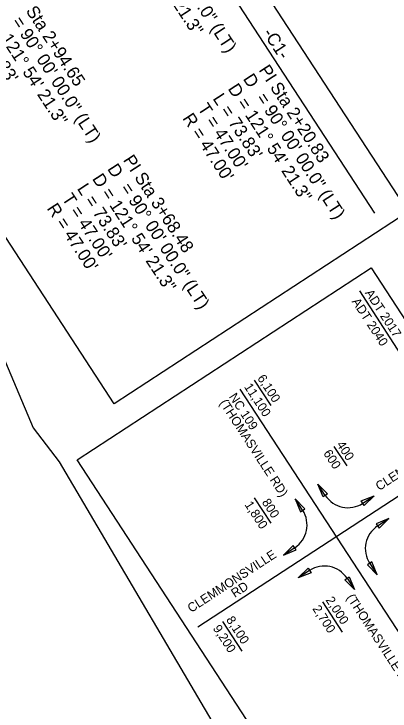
# Model space of a CAD drawing. Extents: x 1639622 to 2864602, y 842655 to 973236.
# Drawn here: x 1640955.4 to 1641163.7, y 843105.8 to 843491.5 of the extents above; entities that cross this region are included whole.
import ezdxf

# ---------------------------------------------------------------- set-up
doc = ezdxf.new("R2010")
doc.units = 0
for name, color, linetype in [('Default', 7, 'Continuous'), ('Prop Horizontal Alignment Curve and Spiral Data', 7, 'Continuous'), ('Sheet Clip Boundary CELL', 7, 'Continuous')]:
    doc.layers.add(name, color=color, linetype=linetype)

msp = doc.modelspace()

# ---------------------------------------------------------------- linework, layer by layer
at = {"layer": 'Default'}
for p, q in [((1641146.66, 843338.21), (1641169.32, 843303.49)), ((1641088.4, 843288.94), (1641097.65, 843274.76)), ((1641080.54, 843283.82), (1641187.11, 843120.51)), ((1641210.87, 843252.44), (1641057.23, 843152.18)), ((1641132.62, 843252.18), (1641139.64, 843241.43)), ((1641127.81, 843225.1), (1641123.71, 843231.39)), ((1641148.57, 843220.74), (1641154.85, 843224.84)), ((1641097.79, 843209.74), (1641088.67, 843223.72)), ((1641115.25, 843216.91), (1641111.15, 843223.19)), ((1641156.77, 843208.18), (1641163.05, 843212.28)), ((1641110.88, 843196.15), (1641104.6, 843192.05)), ((1641152.4, 843187.42), (1641156.5, 843181.14)), ((1641119.08, 843183.59), (1641112.8, 843179.49)), ((1641139.84, 843179.22), (1641143.94, 843172.94)), ((1641126.25, 843166.13), (1641137.14, 843149.45)), ((1641081.77, 843138.9), (1641071.09, 843155.26))]:
    msp.add_line(p, q, dxfattribs=at)
for points in [[(1640990.48, 843244.72), (1641153.27, 843350.95), (1641277.04, 843161.28), (1641114.25, 843055.06)], [(1641123.71, 843231.39), (1641129.07, 843225.92), (1641126.56, 843224.29)], [(1641154.85, 843224.84), (1641149.39, 843219.48), (1641147.75, 843222)], [(1641111.15, 843223.19), (1641113.99, 843216.09), (1641116.51, 843217.73)], [(1641163.05, 843212.28), (1641155.95, 843209.43), (1641157.59, 843206.92)], [(1641104.6, 843192.05), (1641111.7, 843194.89), (1641110.07, 843197.4)], [(1641156.5, 843181.14), (1641153.66, 843188.24), (1641151.15, 843186.6)], [(1641112.8, 843179.49), (1641118.26, 843184.84), (1641119.9, 843182.33)], [(1641143.94, 843172.94), (1641138.59, 843178.4), (1641141.1, 843180.04)]]:
    msp.add_lwpolyline(points, close=True, dxfattribs=at)
for centre, start, end in [((1641140.37, 843233.3), 213.1259, 303.1259), ((1641102.69, 843208.71), 303.1259, 33.1259), ((1641164.97, 843195.62), 123.1259, 213.1259), ((1641127.28, 843171.02), 33.1259, 123.1259)]:
    msp.add_arc(centre, 15, start, end, dxfattribs=at)
at = {"layer": 'Prop Horizontal Alignment Curve and Spiral Data'}
msp.add_line((1641038.07, 843560.52), (1641155.09, 843381.18), dxfattribs=at)
msp.add_lwpolyline([(1641046, 843577.64), (1641173.64, 843382.04), (1641010.85, 843275.81), (1640883.22, 843471.41)], close=True, dxfattribs=at)
at = {"layer": 'Sheet Clip Boundary CELL'}
msp.add_lwpolyline([(1640864.06, 843725.83), (1640845.52, 843547.93), (1640965.98, 843262.45), (1640980.45, 843243.58), (1641082.2, 843071.1), (1640923.46, 842968.82), (1640618.94, 842769.14), (1640215.87, 843383.28), (1640133.11, 843329.87), (1640089.02, 843391.66), (1639884.02, 843719.9), (1639876.38, 843724.64), (1639884.63, 843735.86), (1640061.58, 843856.15), (1640079.07, 843868.65), (1640087.48, 843874.13), (1640138.9, 843902.72), (1640120.5, 843922.53), (1640112.26, 843933.12), (1640009.37, 844107.66), (1640616.07, 844499.65)], dxfattribs=at)

# ---------------------------------------------------------------- texts
at = {"layer": 'Default'}
for s, rotation, p in [('ADT 2017', 303.1259, (1641149.6, 843337.14)), ('ADT 2040', 303.1259, (1641142.27, 843332.36)), ('6,100', 303.1259, (1641089.97, 843289.96)), ('11,100', 303.1259, (1641082.64, 843285.18)), ('NC 109', 303.1259, (1641074.26, 843279.72)), ('(THOMASVILLE RD)', 303.1259, (1641069.02, 843276.3)), ('CLEMMONSVILLE', 33.1259, (1641157.68, 843227.47)), ('400', 303.1259, (1641133.85, 843253.2)), ('600', 303.1259, (1641126.52, 843248.42)), ('1,800', 303.1259, (1641082.91, 843219.96)), ('800', 303.1259, (1641092.48, 843221.31)), ('CLEMMONSVILLE', 33.1259, (1641053.54, 843160.02)), ('RD', 33.1259, (1641077.68, 843168.3)), ('2,000', 303.1259, (1641127.82, 843167.16)), ('(THOMASVILLE RD)', 303.1259, (1641139.31, 843168.58)), ('2,700', 303.1259, (1641120.49, 843162.37)), ('8,100', 303.1259, (1641072.66, 843156.28)), ('9,200', 303.1259, (1641065.34, 843151.5))]:
    msp.add_text(s, height=5, rotation=rotation, dxfattribs=at).set_placement(p)
at = {"layer": 'Prop Horizontal Alignment Curve and Spiral Data'}
for s, p in [('D = 121%%d 54\' 21.3"', (1641013.5, 843542.28)), ('= 90%%d 00\' 00.0" (LT)', (1641029.14, 843537.14)), ('PI Sta 2+94.65', (1640955.49, 843502.82)), ('D = 121%%d 54\' 21.3"', (1640938.37, 843492.45)), ("L = 73.83'", (1640929.99, 843486.99)), ('= 90%%d 00\' 00.0" (LT)', (1640954.01, 843487.31)), ('-C1-', (1641092.96, 843480.98)), ('PI Sta 2+20.83', (1641090.73, 843460.52)), ('D', (1641081.99, 843455.62)), ('D = 121%%d 54\' 21.3"', (1641073.61, 843450.16)), ("L = 73.83'", (1641065.24, 843444.69)), ('= 90%%d 00\' 00.0" (LT)', (1641089.26, 843445.02)), ("T = 47.00'", (1641056.86, 843439.23)), ("R = 47.00'", (1641048.49, 843433.76)), ('PI Sta 3+68.48', (1641015.6, 843410.69)), ('D', (1641006.86, 843405.79)), ('D = 121%%d 54\' 21.3"', (1640998.48, 843400.33)), ("L = 73.83'", (1640990.11, 843394.86)), ('= 90%%d 00\' 00.0" (LT)', (1641014.13, 843395.19)), ("T = 47.00'", (1640981.73, 843389.4)), ("R = 47.00'", (1640973.36, 843383.93))]:
    msp.add_text(s, height=7, rotation=303.1259, dxfattribs=at).set_placement(p)

doc.saveas('drawing.dxf')
